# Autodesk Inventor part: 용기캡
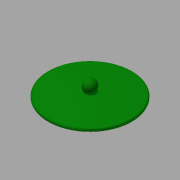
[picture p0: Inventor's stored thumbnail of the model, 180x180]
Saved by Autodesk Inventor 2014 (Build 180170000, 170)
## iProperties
Created: 2018-01
Part Number: 용기캡
Material: ABS 플라스틱
Document SubType Name: Modeling
Designer: mduedu
Density: 1 g/cm^3
Appearance: Dark Green
Author: mduedu
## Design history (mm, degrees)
sketch "스케치1"
  geometry: L1 (-35, 2.5)-(0, 2.5); L2 (0, 5)-(0, 0); L3 (0, 0)-(-35, 0); L4 (-35, 0)-(-35, 2.5); L5 (-31, 0)-(-29, 0); L6 (-29, 0)-(-29, -2); L7 (-29, -2)-(-31, -2); L8 (-31, -2)-(-31, 0); A1 r 246.25 centre (0, -241.25) between (0, 5) and (-35, 2.5); 1 further point
  constraints: 16 end point, 4 parallel, 2 horizontal, 2 perpendicular, 2 point on circle, 1 centre point, 1 coincident, 1 midpoint, 1 point on line, 1 vertical alignment
  dimensions: "d2" = 70 diameter of L4 L2; "d3" = 5 distance from line of L2.start L3; "d4" = 2.5 distance of L3.end L1.start; "d5" = 4 distance between parallel lines of L8 L4; "d6" = 2 distance of L6.end L7.end; "d7" = 2 distance between parallel lines of L7 L3
revolve "회전1" sketch "스케치1" stored, may be unused: angle "d8" = 90 deg
chamfer "모따기1" distance "d9" = 0.5; stored, may be unused: second distance "d10" = 2, angle "d11" = 45 deg
fillet "모깎기1" dims "d12" = 1
fillet "모깎기2" dims "d13" = 1
sketch "스케치2"
  geometry: L1 (-30.5, -2)-(-31, -1.5) reference; L2 (-31, -1.5)-(-31, 0) reference; L3 (-31, 0)-(-34, 0) reference; L4 (-35, 1)-(-35, 1.632) reference; L5 (35, 1.632)-(35, 1) reference; L6 (34, 0)-(31, 0) reference; L7 (31, 0)-(31, -1.5) reference; L8 (31, -1.5)-(30.5, -2) reference; L9 (30.5, -2)-(29, -2) reference; L10 (29, -2)-(29, -1) reference; L11 (28, 0)-(-28, 0) reference; L12 (-29, -1)-(-29, -2) reference; L13 (-29, -2)-(-30.5, -2) reference; L14 (0, 14)-(0, 4); A1 r 1 centre (-34, 1) between (-35, 1) and (-34, 0) reference; A2 r 1 centre (-34, 1.632) between (-34.139, 2.622) and (-35, 1.632) reference; A3 r 246.25 centre (0, -241.25) between (34.139, 2.622) and (-34.139, 2.622) reference; A4 r 1 centre (34, 1.632) between (35, 1.632) and (34.139, 2.622) reference; A5 r 1 centre (34, 1) between (34, 0) and (35, 1) reference; A6 r 1 centre (28, -1) between (29, -1) and (28, 0) reference; A7 r 1 centre (-28, -1) between (-28, 0) and (-29, -1) reference; A8 r 5 centre (0, 9) between (0, 14) and (0, 4); 3 further points
  constraints: 2 end point, 2 midpoint, 2 point on circle, 1 centre point, 1 coincident, 1 perpendicular, 1 point on line, 1 vertical alignment
  dimensions: "d14" = 10 diameter of A8; "d16" = 9 distance of A8.centre point (0, 0)
revolve "회전2" sketch "스케치2" stored, may be unused: angle "d17" = 90 deg
fillet "모깎기3" dims "d18" = 1
node "솔리드1"
node "절단 모서리 투영1"
